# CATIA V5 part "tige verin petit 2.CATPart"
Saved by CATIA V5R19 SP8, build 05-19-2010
Part number: tige verin petit 2
Bounding box of the stored display mesh (mm): x -12 to 14.392, y -54 to -48, z 107.711 to 149.853
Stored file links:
  G:\EU_thinkMotion\CFAO_2010\MMS_groupe1\MMS_groupe1\A reprendre\OK\glenerrant\glenerrant\glenerrant\tige verin petit 2.CATPart
  C:\Users\Gauthier\Documents\IFMA\Projet CFAO\Systeme.CATProduct
  G:\EU_thinkMotion\CFAO_2010\MMS_groupe1\MMS_groupe1\A reprendre\OK\glenerrant\glenerrant\glenerrant\corps verin petit 2.CATPart
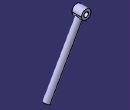
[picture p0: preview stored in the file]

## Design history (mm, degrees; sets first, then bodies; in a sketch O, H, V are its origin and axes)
Set1
  Plane1: linked copy from another document
Set2
  Point1: (-9, -51, 147)
  Point2: (17, -51, 101)
  Point3: (-9, 51, 147)
  Line1: type PtPt, FirstPoint Point3, SecondPoint Point1
  Line2: type PtPt, FirstPoint Point2, SecondPoint Point1
  Plane2: type Normal, Curve Line2, RefPoint Point1
Body1 (main body)
  Sketch1 on Plane1, origin (0, -51, 0), H (-1, 0, 0), V (0, 0, 1)
    circle A1 centre (9, 147) radius 1.5
    point P1 (9, 147)
    circle A2 centre (9, 147) radius 3
    point P2 (9, 147)
    reference projected point E1 (9, 147) from Point1
    reference projected point E2 (9, 147) from Point1
    radius A2 = 3
    radius A1 = 1.5
    coincidence: P1 E1, P2 E2
  Pad1: profile Sketch1, direction (0, 1, 0), length 3, opposite side length 3
  Sketch2 on Plane2, origin (-65.149, 0, 115.2636), H (0, -1, 0), V (0.8706, 0, 0.4921)
    circle A1 centre (51, 64.4974) radius 2
    point P1 (51, 64.4974)
    reference projected point E1 (51, 64.4974) from Point1
    radius A1 = 2
    coincidence: P1 E1
  Pad2: profile Sketch2, direction (0.4921, 0, -0.8706), length 44, opposite side length -2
